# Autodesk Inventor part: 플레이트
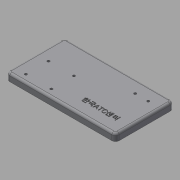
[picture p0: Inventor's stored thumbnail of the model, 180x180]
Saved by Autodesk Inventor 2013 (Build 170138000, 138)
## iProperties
Created: 2018-01
Part Number: 플레이트
Material: 알루미늄 6061
Document SubType Name: Modeling
Designer: mduedu
Density: 2.71 g/cm^3
Author: mduedu
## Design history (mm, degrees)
sketch "스케치1"
  geometry: L1 (75, 40)-(-75, 40); L2 (-75, 40)-(-75, -40); L3 (-75, -40)-(75, -40); L4 (75, -40)-(75, 40); L5 (75, 40)-(-75, -40); L6 (-75, 40)-(75, -40); 1 further point
  constraints: 12 end point, 2 midpoint, 2 parallel, 1 horizontal, 1 perpendicular
  dimensions: "d0" = 150 distance of L3.end L2.end; "d1" = 80 distance of L2.end L1.end
extrude "돌출1" new body sketch "스케치1" distance "d2" = 10; taper "d3" = 0 deg
fillet "모깎기1" dims "d4" = 5
fillet "모깎기2" dims "d5" = 3
sketch "스케치2"
  geometry: L1 (-70, 40)-(70, 40) reference; L2 (-75, -35)-(-75, 35) reference; 5 further points
  constraints: 2 horizontal alignment, 2 vertical alignment
  dimensions: "d6" = 10 distance from line of point (-58, 30) L1; "d7" = 35 distance of point (-23, 30) point (-58, 30); "d8" = 31 distance of point (-58, -1) point (-58, 30); "d9" = 17 distance from line of point (-58, 30) L2
sketch "스케치3"
  geometry: 4 further points
  constraints: 4 other
hole "구멍1" sketch "스케치3" at (-23, 30), (-58, -1), (-23, -1), (-58, 30) diameter "d10" = 3.4; stored, may be unused: countersink angle "d14" = 90 deg, drill point angle "d16" = 0 deg; dims "d11" = 6, "d12" = 6.5, "d13" = 3.4, "d15" = 8
sketch "스케치4"
  geometry: L1 (75, 35)-(75, -35) reference; L2 (70, -40)-(-70, -40) reference; 3 further points
  constraints: 1 horizontal alignment
  dimensions: "d17" = 17 distance from line of point (58, -22) L1; "d18" = 18 distance of point (40, -22) point (58, -22); "d19" = 18 distance from line of point (58, -22) L2
sketch "스케치5"
  geometry: 2 further points
  constraints: 2 other
hole "구멍2" sketch "스케치5" at (40, -22), (58, -22) diameter "d20" = 3.4; stored, may be unused: countersink angle "d24" = 90 deg, drill point angle "d26" = 0 deg; dims "d21" = 6, "d22" = 6.5, "d23" = 3.4, "d25" = 8
sketch "스케치6"
  geometry: L1 (75, -35)-(75, 35) reference; L2 (-70, -40)-(70, -40) reference; 2 further points
  constraints: 1 other
  dimensions: "d27" = 40 distance from line of point (35, -20) L1; "d28" = 20 distance from line of point (35, -20) L2
feature "엠보싱1" sketch "스케치6" dims "d0" = 150, "d29" = 0.5, "d30" = 0
node "솔리드1"
